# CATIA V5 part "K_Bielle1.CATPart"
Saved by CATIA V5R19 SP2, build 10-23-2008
Part number: Bielle1
Bounding box of the stored display mesh (mm): x 0 to 1, y -1 to 1, z -1 to 25
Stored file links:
  G:\Khaled_CFAO_2011\ST2M\ST2M_GR1\bgaltie\bgaltie\Khaled\CAD_thinkMOTION\K_Bielle1.CATPart
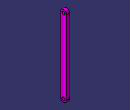
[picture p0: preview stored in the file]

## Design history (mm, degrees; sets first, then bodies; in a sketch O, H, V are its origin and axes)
AxisSystem1: origin (0, 0, 0), X (1, 0, 0), Y (0, 1, 0), Z (0, 0, 1)
Body1 (main body)
  Sketch1 on YZ plane of AxisSystem1, origin (0, 0, 0), H (0, 1, 0), V (0, 0, 1)
    construction line L1 (0, 0) -> (0, 24)
    point P1 (0, 0)
    point P2 (0, 24)
    line L2 (-1, 0) -> (-1, 24)
    line L3 (1, 24) -> (1, 0)
    arc A1 centre (0, 24) radius 1 from (-1, 24) to (1, 24) cw
    arc A2 centre (0, 0) radius 1 from (1, 0) to (-1, 0) cw
    circle A3 centre (0, 24) radius 0.5
    point P7 (0, 24)
    point P8 (0, 0)
    circle A4 centre (0, 0) radius 0.5
    distance L1 L2 = 1
    length L1 = 24
    radius A3 = 0.5
    radius A4 = 0.5
    vertical: L1 V
    tangency: A1 L2, A2 L2, A1 L3, A2 L3
    coincidence: P1 O, P8 O, P7 P2
  Pad1: profile Sketch1, direction (1, 0, 0), length 1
